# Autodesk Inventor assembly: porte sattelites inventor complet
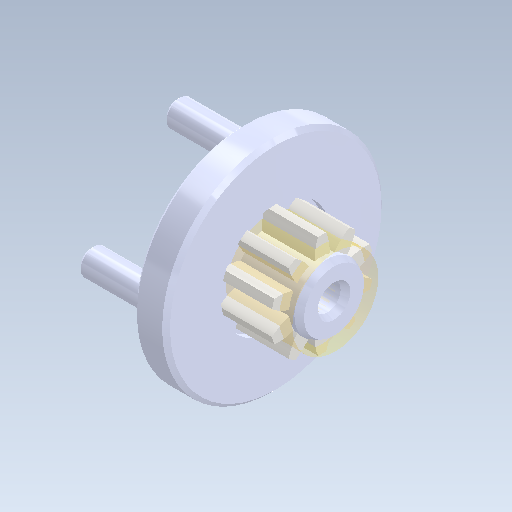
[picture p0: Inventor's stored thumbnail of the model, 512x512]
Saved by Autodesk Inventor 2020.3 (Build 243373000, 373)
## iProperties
Created: 2020-11
Part Number: porte sattelites inventor complet
Document SubType Name: Assembly
Designer: ficho
Mass: 1.5637 g
Surface Area: 10.4863 cm^2
Volume: 0.739564 cm^3
Density: 2.11435 g/cm^3
Author: ficho
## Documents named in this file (3)
- D:\travail\année 2020-2021\2I2D\laveur de vitre\Lave vitre\4 Dossier Ressources\1 Modèles 3D Solidworks\adaptation inventor\porte sattelites inventor complet.iam
- D:\travail\année 2020-2021\2I2D\laveur de vitre\Lave vitre\4 Dossier Ressources\1 Modèles 3D Solidworks\adaptation inventor\Porte sattelites inventor.ipt
- D:\travail\année 2020-2021\2I2D\laveur de vitre\Lave vitre\4 Dossier Ressources\1 Modèles 3D Solidworks\adaptation inventor\satellite.ipt
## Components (2 placed, 2 different names)
1. Porte sattelites inventor:1 — Logement:1
2. Engrenage cylindrique2:1 — Logement:1
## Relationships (1: Insert 1)
- Logement:1 [Insert]: Porte sattelites inventor:1 ↔ Engrenage cylindrique2:1
